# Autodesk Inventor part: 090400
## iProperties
Shininess: 69.0
Length Units: 11269
Angle Units: 11279
Time Units: 11290
Mass Units: 11284
Length Display Precision: 3
Angle Display Precision: 2
Compacted: True
Company: Pneumax S.p.A.
Part Number: 090400
Material: Default
Description: TAPPO Ø4
Document SubType Name: Modellazione
Catalog Web Link: www.pneumaxspa.com
Density: 1.59
Volumn: 0.8648857994912436
Area: 17.092995283760587
PropertySet Name: Model Information
Control State: 0
Master: False
Checked Out: False
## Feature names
1. Chamfer10
